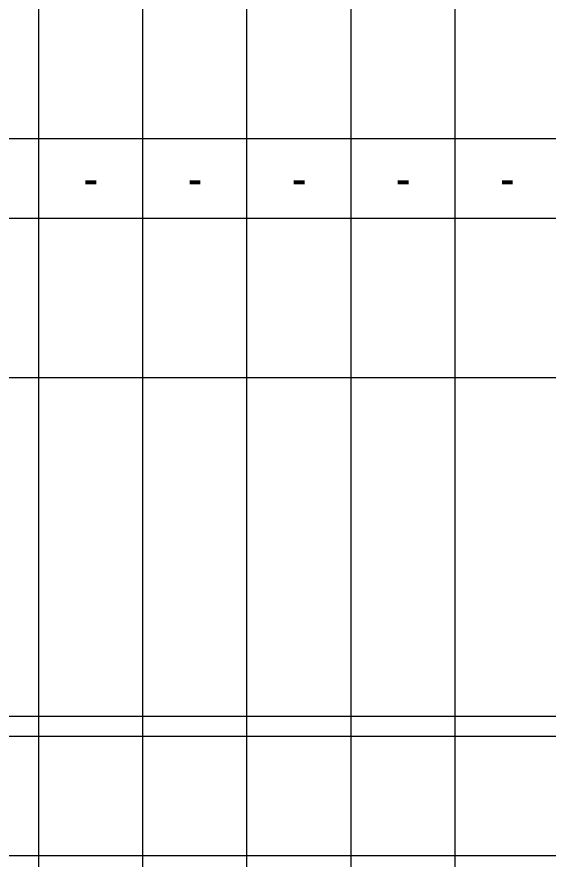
# Model space of a CAD drawing. Extents: x -0.01 to 0.83, y -0.63 to 1.27.
# Drawn here: x 0.6165 to 0.7228, y -0.0007 to 0.1679 of the extents above; entities that cross this region are included whole.
import ezdxf

# ---------------------------------------------------------------- set-up
doc = ezdxf.new("R2010")
doc.units = 0

msp = doc.modelspace()

# ---------------------------------------------------------------- linework, layer by layer
msp.add_lwpolyline([(0, 0), (0.83333, 0), (0.83333, 1.275), (0, 1.275)], close=True)
msp.add_lwpolyline([(0, 0), (0.83333, 0), (0.83333, 1.275), (0, 1.275)], close=True)
msp.add_lwpolyline([(0, 0), (0.83333, 0), (0.83333, 1.275), (0, 1.275)], close=True)
msp.add_lwpolyline([(0, 0), (0.83333, 0), (0.83333, 1.275), (0, 1.275)], close=True)
msp.add_lwpolyline([(0, 0), (0.83333, 0), (0.83333, 1.275), (0, 1.275)], close=True)
for points in [[(0.6625, 1.22083), (0.6625, -0.62183)], [(0.62083, 1.20833), (0.62083, -0.62183)], [(0.64167, 1.20833), (0.64167, -0.62183)], [(0.68333, 1.20833), (0.68333, -0.62183)], [(0.70417, 1.20833), (0.70417, -0.62183)], [(0.6, 0.1435), (0.62083, 0.1435)], [(0.62083, 0.1435), (0.64167, 0.1435)], [(0.64167, 0.1435), (0.6625, 0.1435)], [(0.6625, 0.1435), (0.68333, 0.1435)], [(0.68333, 0.1435), (0.70417, 0.1435)], [(0.70417, 0.1435), (0.725, 0.1435)], [(0.6, 0.12756), (0.62083, 0.12756)], [(0.62083, 0.12756), (0.64167, 0.12756)], [(0.64167, 0.12756), (0.6625, 0.12756)], [(0.6625, 0.12756), (0.68333, 0.12756)], [(0.68333, 0.12756), (0.70417, 0.12756)], [(0.70417, 0.12756), (0.725, 0.12756)], [(0.6, 0.09567), (0.62083, 0.09567)], [(0.62083, 0.09567), (0.64167, 0.09567)], [(0.64167, 0.09567), (0.6625, 0.09567)], [(0.6625, 0.09567), (0.68333, 0.09567)], [(0.68333, 0.09567), (0.70417, 0.09567)], [(0.70417, 0.09567), (0.725, 0.09567)], [(0.6, 0.0279), (0.62083, 0.0279)], [(0.62083, 0.0279), (0.64167, 0.0279)], [(0.64167, 0.0279), (0.6625, 0.0279)], [(0.6625, 0.0279), (0.68333, 0.0279)], [(0.68333, 0.0279), (0.70417, 0.0279)], [(0.70417, 0.0279), (0.725, 0.0279)], [(0.6, 0.02392), (0.62083, 0.02392)], [(0.62083, 0.02392), (0.64167, 0.02392)], [(0.64167, 0.02392), (0.6625, 0.02392)], [(0.6625, 0.02392), (0.68333, 0.02392)], [(0.68333, 0.02392), (0.70417, 0.02392)], [(0.70417, 0.02392), (0.725, 0.02392)], [(0, 0), (0.83333, 0)]]:
    msp.add_lwpolyline(points)

# ---------------------------------------------------------------- texts
for p in [(0.62984, 0.13219), (0.65068, 0.13219), (0.67151, 0.13219), (0.69234, 0.13219), (0.71318, 0.13219)]:
    msp.add_text('-', height=0.00667).set_placement(p)

doc.saveas('drawing.dxf')
